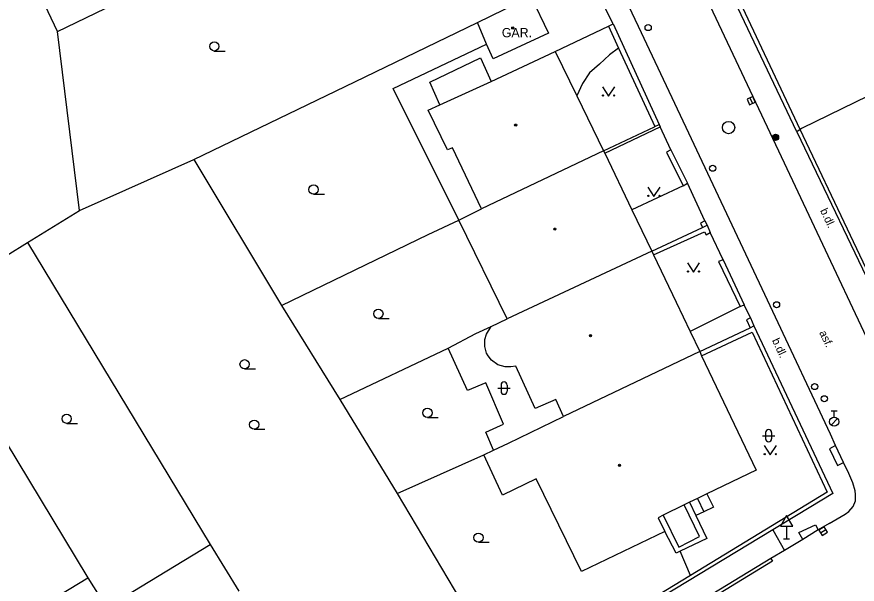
# Model space of a CAD drawing. Extents: x -600391 to -599491, y -1160176 to -1159402.
# Drawn here: x -600105.3 to -600037.1, y -1160099.5 to -1160053.5 of the extents above; entities that cross this region are included whole.
import ezdxf

# ---------------------------------------------------------------- set-up
doc = ezdxf.new("R2010")
doc.units = 0
for name, color, linetype in [('Level 10', 7, 'Continuous'), ('Level 11', 7, 'Continuous'), ('Level 25', 7, 'Continuous'), ('Level 27', 7, 'Continuous'), ('Level 28', 7, 'Continuous'), ('Level 34', 7, 'Continuous'), ('Level 36', 7, 'Continuous'), ('Level 39', 7, 'Continuous'), ('Level 40', 7, 'Continuous'), ('Level 41', 7, 'Continuous'), ('Level 5', 7, 'Continuous'), ('Level 51', 7, 'Continuous'), ('Level 7', 7, 'Continuous'), ('Level 8', 7, 'Continuous')]:
    doc.layers.add(name, color=color, linetype=linetype)

msp = doc.modelspace()

# ---------------------------------------------------------------- linework, layer by layer
at = {"layer": 'Level 10'}
for points in [[(-600033.19, -1160086.1), (-600042.96, -1160065.38), (-600049.67, -1160051.14), (-600054.09, -1160041.8), (-600054.53, -1160040.87)], [(-600038.81, -1160088.3), (-600039.24, -1160087.36), (-600043.9, -1160077.43), (-600044.33, -1160076.51), (-600050.3, -1160063.87), (-600050.73, -1160062.95), (-600054.15, -1160055.73), (-600054.58, -1160054.81), (-600058.59, -1160046.27), (-600059.02, -1160045.36), (-600059.46, -1160044.45), (-600059.92, -1160043.53)], [(-600038.18, -1160089.66), (-600038.81, -1160088.3)], [(-600039.34, -1160094.63), (-600038.05, -1160093.86), (-600037.74, -1160093.66), (-600037.39, -1160093.24), (-600037.19, -1160092.79), (-600037.19, -1160092.28), (-600037.22, -1160091.97), (-600037.41, -1160091.33), (-600037.74, -1160090.57), (-600038.18, -1160089.66)], [(-600039.34, -1160094.63), (-600040.22, -1160095.14)], [(-600040.22, -1160095.14), (-600041.48, -1160095.93)], [(-600041.48, -1160095.93), (-600042.96, -1160096.82)], [(-600042.96, -1160096.82), (-600044.07, -1160097.47)], [(-600044.07, -1160097.47), (-600060.7, -1160107.59), (-600078.93, -1160118.69), (-600104.94, -1160134.34), (-600126.03, -1160147.1), (-600156.25, -1160165.27)]]:
    msp.add_lwpolyline(points, dxfattribs=at)
at = {"layer": 'Level 11'}
for points in [[(-600057.26, -1160054.27), (-600056.87, -1160054.08)], [(-600061.59, -1160056.32), (-600057.26, -1160054.27)], [(-600056.44, -1160056.05), (-600057.18, -1160056.59), (-600057.98, -1160057.33), (-600058.79, -1160058.05), (-600059.36, -1160058.9), (-600059.83, -1160059.92)], [(-600051.18, -1160067.21), (-600055.35, -1160069.16)], [(-600038.81, -1160088.3), (-600039.31, -1160088.55), (-600038.67, -1160089.91), (-600038.18, -1160089.66)], [(-600049.27, -1160092.22), (-600048.74, -1160093.3), (-600049.51, -1160093.67)], [(-600050.67, -1160092.9), (-600050.16, -1160093.98)], [(-600050.02, -1160092.59), (-600049.51, -1160093.67)], [(-600052.82, -1160093.95), (-600051.54, -1160096.53), (-600049.85, -1160095.69), (-600051.12, -1160093.12)], [(-600049.51, -1160093.67), (-600050.16, -1160093.98)], [(-600050.16, -1160093.98), (-600049.28, -1160095.83), (-600051.44, -1160096.88), (-600051.76, -1160097.03), (-600052.67, -1160095.26)], [(-600041.48, -1160095.93), (-600041.79, -1160095.36), (-600040.45, -1160094.73), (-600040.22, -1160095.14)], [(-600043.91, -1160095.14), (-600042.96, -1160096.82)], [(-600044.07, -1160097.47), (-600043.93, -1160097.69), (-600050.62, -1160101.76), (-600060.21, -1160107.58)]]:
    msp.add_lwpolyline(points, dxfattribs=at)
at = {"layer": 'Level 25'}
for radius in [0.25, 0.2, 0.15, 0.1, 0.05]:
    msp.add_circle((-600043.69, -1160063.28), radius, dxfattribs=at)
at = {"layer": 'Level 27'}
for p, q in [((-600045.771, -1160060.081), (-600045.569, -1160060.539)), ((-600040.031, -1160095.385), (-600039.609, -1160095.115))]:
    msp.add_line(p, q, dxfattribs=at)
for points in [[(-600046, -1160060.182), (-600045.798, -1160060.64), (-600045.34, -1160060.438), (-600045.542, -1160059.98)], [(-600039.896, -1160095.595), (-600039.475, -1160095.326), (-600039.744, -1160094.905), (-600040.165, -1160095.174)]]:
    msp.add_lwpolyline(points, close=True, dxfattribs=at)
msp.add_circle((-600047.5, -1160062.49), 0.5, dxfattribs=at)
at = {"layer": 'Level 28'}
for p, q in [((-600039.18, -1160085.485), (-600038.68, -1160085.485)), ((-600038.93, -1160085.985), (-600038.93, -1160085.485)), ((-600039.188, -1160086.632), (-600038.658, -1160086.102))]:
    msp.add_line(p, q, dxfattribs=at)
for centre, radius in [((-600054.03, -1160054.37), 0.25), ((-600048.79, -1160065.79), 0.25), ((-600043.61, -1160076.87), 0.25), ((-600040.52, -1160083.51), 0.25), ((-600039.73, -1160084.5), 0.25), ((-600038.93, -1160086.36), 0.375)]:
    msp.add_circle(centre, radius, dxfattribs=at)
at = {"layer": 'Level 34'}
for p, q in [((-600042.8, -1160094.852), (-600042.8, -1160095.87)), ((-600043.05, -1160095.87), (-600042.55, -1160095.87))]:
    msp.add_line(p, q, dxfattribs=at)
msp.add_lwpolyline([(-600043.3, -1160094.852), (-600042.3, -1160094.852), (-600042.8, -1160093.986)], close=True, dxfattribs=at)
at = {"layer": 'Level 36'}
for p, q in [((-600089.25, -1160056.275), (-600088.375, -1160056.275)), ((-600081.19, -1160067.895), (-600080.315, -1160067.895)), ((-600075.93, -1160077.975), (-600075.055, -1160077.975)), ((-600086.79, -1160082.075), (-600085.915, -1160082.075)), ((-600065.976, -1160083.386), (-600065.976, -1160083.886)), ((-600065.476, -1160083.386), (-600065.476, -1160083.886)), ((-600066.226, -1160083.636), (-600065.226, -1160083.636)), ((-600071.95, -1160086.015), (-600071.075, -1160086.015)), ((-600101.23, -1160086.495), (-600100.355, -1160086.495)), ((-600086.01, -1160086.975), (-600085.135, -1160086.975)), ((-600044.756, -1160087.496), (-600043.756, -1160087.496)), ((-600044.506, -1160087.246), (-600044.506, -1160087.746)), ((-600044.006, -1160087.246), (-600044.006, -1160087.746)), ((-600067.81, -1160096.145), (-600066.935, -1160096.145))]:
    msp.add_line(p, q, dxfattribs=at)
for points in [[(-600057.74, -1160059.19), (-600057.24, -1160059.94), (-600056.74, -1160059.19)], [(-600054.06, -1160067.33), (-600053.56, -1160068.08), (-600053.06, -1160067.33)], [(-600050.85, -1160073.47), (-600050.35, -1160074.22), (-600049.85, -1160073.47)], [(-600044.62, -1160088.3), (-600044.12, -1160089.05), (-600043.62, -1160088.3)]]:
    msp.add_lwpolyline(points, dxfattribs=at)
for centre, radius in [((-600089.25, -1160055.9), 0.375), ((-600057.69, -1160059.89), 0.05), ((-600056.791, -1160059.89), 0.05), ((-600081.19, -1160067.52), 0.375), ((-600054.01, -1160068.03), 0.05), ((-600053.111, -1160068.03), 0.05), ((-600050.8, -1160074.17), 0.05), ((-600049.901, -1160074.17), 0.05), ((-600075.93, -1160077.6), 0.375), ((-600086.79, -1160081.7), 0.375), ((-600071.95, -1160085.64), 0.375), ((-600101.23, -1160086.12), 0.375), ((-600086.01, -1160086.6), 0.375), ((-600044.57, -1160089), 0.05), ((-600043.671, -1160089), 0.05), ((-600067.81, -1160095.77), 0.375)]:
    msp.add_circle(centre, radius, dxfattribs=at)
for centre, start, end in [((-600065.726, -1160083.386), 0, 180), ((-600065.726, -1160083.886), 180, 0), ((-600044.256, -1160087.246), 0, 180), ((-600044.256, -1160087.746), 180, 0)]:
    msp.add_arc(centre, 0.25, start, end, dxfattribs=at)
at = {"layer": 'Level 39'}
for centre, radius in [((-600065.02, -1160054.4), 0.09), ((-600065.02, -1160054.4), 0.0398), ((-600064.78, -1160062.29), 0.09), ((-600064.78, -1160062.29), 0.0398), ((-600061.61, -1160070.73), 0.09), ((-600061.61, -1160070.73), 0.0398), ((-600058.71, -1160079.38), 0.09), ((-600058.71, -1160079.38), 0.0398), ((-600056.36, -1160089.91), 0.09), ((-600056.36, -1160089.91), 0.0398)]:
    msp.add_circle(centre, radius, dxfattribs=at)
at = {"layer": 'Level 5'}
for points in [[(-600067.89, -1160053.97), (-600063.56, -1160051.83)], [(-600063.56, -1160051.83), (-600062.13, -1160054.84)], [(-600067.14, -1160055.71), (-600067.89, -1160053.97)], [(-600062.13, -1160054.84), (-600066.62, -1160056.9)], [(-600066.62, -1160056.9), (-600067.14, -1160055.71)], [(-600066.77, -1160058.74), (-600061.59, -1160056.32)], [(-600061.59, -1160056.32), (-600059.83, -1160059.92), (-600057.65, -1160064.37)], [(-600070.95, -1160060.65), (-600066.77, -1160058.74)], [(-600071.88, -1160061.08), (-600070.95, -1160060.65)], [(-600070.32, -1160064.29), (-600071.88, -1160061.08)], [(-600069.9, -1160064.13), (-600070.32, -1160064.29)], [(-600067.55, -1160069.09), (-600069.9, -1160064.13)], [(-600057.65, -1160064.37), (-600067.55, -1160069.09)], [(-600057.65, -1160064.37), (-600057.55, -1160064.58)], [(-600057.55, -1160064.58), (-600055.35, -1160069.16), (-600053.74, -1160072.53)], [(-600069.41, -1160070.01), (-600067.55, -1160069.09)], [(-600065.47, -1160078.02), (-600069.41, -1160070.01)], [(-600053.74, -1160072.53), (-600065.47, -1160078.02)], [(-600053.74, -1160072.53), (-600053.6, -1160072.83)], [(-600053.6, -1160072.83), (-600051.76, -1160076.66)], [(-600051.76, -1160076.66), (-600050.63, -1160079.03)], [(-600067.15, -1160079.26), (-600066.78, -1160078.63)], [(-600066.78, -1160078.63), (-600065.47, -1160078.02)], [(-600067.29, -1160079.69), (-600067.15, -1160079.26)], [(-600050.63, -1160079.03), (-600049.84, -1160080.67)], [(-600067.3, -1160080.25), (-600067.29, -1160079.69)], [(-600067.14, -1160080.81), (-600067.3, -1160080.25)], [(-600049.84, -1160080.67), (-600060.91, -1160085.95)], [(-600049.84, -1160080.67), (-600049.69, -1160081.01)], [(-600067.03, -1160081.02), (-600067.14, -1160080.81)], [(-600066.76, -1160081.36), (-600067.03, -1160081.02)], [(-600066.22, -1160081.75), (-600066.76, -1160081.36)], [(-600049.69, -1160081.01), (-600045.26, -1160090.3)], [(-600065.65, -1160081.92), (-600066.22, -1160081.75)], [(-600065.18, -1160081.92), (-600065.65, -1160081.92)], [(-600064.78, -1160081.84), (-600065.18, -1160081.92)], [(-600063.21, -1160085.28), (-600064.78, -1160081.84)], [(-600061.53, -1160084.55), (-600063.21, -1160085.28)], [(-600060.91, -1160085.95), (-600061.53, -1160084.55)], [(-600065.37, -1160088.09), (-600060.91, -1160085.95)], [(-600066.58, -1160088.67), (-600065.37, -1160088.09)], [(-600067.38, -1160089.05), (-600066.58, -1160088.67)], [(-600065.86, -1160092.32), (-600067.38, -1160089.05)], [(-600045.26, -1160090.3), (-600049.27, -1160092.22)], [(-600063.13, -1160090.99), (-600065.86, -1160092.32)], [(-600059.45, -1160098.53), (-600063.13, -1160090.99)], [(-600049.27, -1160092.22), (-600050.02, -1160092.59)], [(-600050.67, -1160092.9), (-600051.12, -1160093.12)], [(-600050.02, -1160092.59), (-600050.67, -1160092.9)], [(-600051.12, -1160093.12), (-600052.82, -1160093.95)], [(-600052.82, -1160093.95), (-600053.23, -1160094.15)], [(-600053.23, -1160094.15), (-600052.67, -1160095.26)], [(-600052.67, -1160095.26), (-600059.45, -1160098.53)]]:
    msp.add_lwpolyline(points, dxfattribs=at)
at = {"layer": 'Level 51'}
for points in [[(-600101.98, -1160054.68), (-600106.28, -1160045.59)], [(-600101.98, -1160054.68), (-600084.89, -1160046.42), (-600083.48, -1160045.74)], [(-600077.85, -1160058.77), (-600067.89, -1160053.97)], [(-600100.19, -1160069.23), (-600101.98, -1160054.68)], [(-600074.72, -1160059.33), (-600067.14, -1160055.71)], [(-600071.76, -1160058.81), (-600067.63, -1160056.82)], [(-600067.63, -1160056.82), (-600066.77, -1160058.74)], [(-600090.92, -1160065.08), (-600077.85, -1160058.77)], [(-600070.95, -1160060.65), (-600071.76, -1160058.81)], [(-600069.41, -1160070.01), (-600074.72, -1160059.33)], [(-600100.19, -1160069.23), (-600090.92, -1160065.08)], [(-600090.92, -1160065.08), (-600083.8, -1160076.92)], [(-600104.41, -1160071.82), (-600100.19, -1160069.23)], [(-600071.89, -1160071.18), (-600069.41, -1160070.01)], [(-600083.8, -1160076.92), (-600071.89, -1160071.18)], [(-600107.73, -1160073.86), (-600104.41, -1160071.82)], [(-600104.41, -1160071.82), (-600089.58, -1160096.34)], [(-600112.89, -1160076.92), (-600099.51, -1160099.02)], [(-600083.8, -1160076.92), (-600079.06, -1160084.57)], [(-600046.55, -1160077.02), (-600050.63, -1160079.03)], [(-600068.01, -1160079.21), (-600066.78, -1160078.63)], [(-600070.26, -1160080.38), (-600068.01, -1160079.21)], [(-600079.06, -1160084.57), (-600070.26, -1160080.38)], [(-600068.7, -1160083.83), (-600070.26, -1160080.38)], [(-600067.21, -1160083.2), (-600068.7, -1160083.83)], [(-600065.76, -1160086.56), (-600067.21, -1160083.2)], [(-600079.06, -1160084.57), (-600074.4, -1160092.18)], [(-600067.21, -1160087.22), (-600066.03, -1160086.68)], [(-600066.03, -1160086.68), (-600065.76, -1160086.56)], [(-600066.58, -1160088.67), (-600067.21, -1160087.22)], [(-600074.4, -1160092.18), (-600067.38, -1160089.05)], [(-600098.01, -1160101.44), (-600089.58, -1160096.34)], [(-600089.58, -1160096.34), (-600087.27, -1160100.11)], [(-600050.59, -1160098.83), (-600051.44, -1160096.88)], [(-600109.89, -1160105.3), (-600099.51, -1160099.02)], [(-600099.51, -1160099.02), (-600098.01, -1160101.44)]]:
    msp.add_lwpolyline(points, dxfattribs=at)
at = {"layer": 'Level 7'}
for points in [[(-600041.68, -1160062.64), (-600054.1, -1160036.27), (-600048.77, -1160031.93), (-600048.15, -1160031.43)], [(-600041.96, -1160062.84), (-600054.46, -1160036.54), (-600054.65, -1160036.14), (-600052.36, -1160034.28), (-600051.73, -1160033.77), (-600051.13, -1160033.27), (-600049.14, -1160031.65)], [(-600056.87, -1160054.08), (-600053.15, -1160062.24)], [(-600057.26, -1160054.27), (-600056.44, -1160056.05), (-600053.5, -1160062.41)], [(-600032.98, -1160058.36), (-600041.53, -1160062.53), (-600041.68, -1160062.64)], [(-600053.5, -1160062.41), (-600053.15, -1160062.24)], [(-600053.15, -1160062.24), (-600053.06, -1160062.44)], [(-600057.65, -1160064.37), (-600053.52, -1160062.42), (-600053.5, -1160062.41)], [(-600057.55, -1160064.58), (-600053.06, -1160062.44)], [(-600041.68, -1160062.64), (-600041.96, -1160062.84)], [(-600041.96, -1160062.84), (-600035.07, -1160077.24), (-600029.76, -1160088.61), (-600029.43, -1160089.27), (-600028.95, -1160089.96), (-600028.33, -1160090.62), (-600027.64, -1160091.15)], [(-600029.44, -1160088.45), (-600041.68, -1160062.64)], [(-600052.2, -1160064.3), (-600052.54, -1160064.49), (-600051.18, -1160067.21), (-600050.83, -1160067.01)], [(-600052.2, -1160064.3), (-600050.83, -1160067.01)], [(-600049.42, -1160070.07), (-600049.79, -1160070.25), (-600049.62, -1160070.6)], [(-600049.62, -1160070.6), (-600049.24, -1160070.42)], [(-600049.42, -1160070.07), (-600049.24, -1160070.42)], [(-600049.24, -1160070.42), (-600049, -1160071)], [(-600053.74, -1160072.53), (-600049.62, -1160070.6)], [(-600053.6, -1160072.83), (-600049.46, -1160070.94), (-600049.33, -1160071.19), (-600049, -1160071)], [(-600047.95, -1160073.21), (-600048.31, -1160073.36)], [(-600047.95, -1160073.21), (-600046.24, -1160076.87)], [(-600048.31, -1160073.36), (-600046.55, -1160077.02)], [(-600046.55, -1160077.02), (-600046.24, -1160076.87)], [(-600045.72, -1160077.94), (-600046.05, -1160078.09)], [(-600045.72, -1160077.94), (-600045.44, -1160078.59)], [(-600046.05, -1160078.09), (-600045.75, -1160078.74)], [(-600045.75, -1160078.74), (-600045.44, -1160078.59)], [(-600045.44, -1160078.59), (-600039.03, -1160092.19)], [(-600049.69, -1160081.01), (-600045.6, -1160079.1), (-600039.51, -1160092.08), (-600050.59, -1160098.83), (-600055.99, -1160102.12), (-600055.84, -1160102.36)], [(-600049.84, -1160080.67), (-600045.75, -1160078.74)], [(-600074.4, -1160092.18), (-600065.15, -1160107.78)], [(-600039.03, -1160092.19), (-600043.91, -1160095.14)], [(-600043.91, -1160095.14), (-600055.84, -1160102.36)]]:
    msp.add_lwpolyline(points, dxfattribs=at)
at = {"layer": 'Level 8'}
for points in [[(-600056.87, -1160054.08), (-600058.78, -1160050.22)], [(-600052.2, -1160064.3), (-600053.06, -1160062.44)], [(-600049.42, -1160070.07), (-600050.83, -1160067.01)], [(-600047.95, -1160073.21), (-600049, -1160071)], [(-600045.72, -1160077.94), (-600046.24, -1160076.87)]]:
    msp.add_lwpolyline(points, dxfattribs=at)

# ---------------------------------------------------------------- texts
at = {"layer": 'Level 40'}
for s, rotation, p in [('b.dl. ', 295.2, (-600040.09, -1160069.22)), ('asf.', 295.27, (-600040.16, -1160079.13)), ('b.dl. ', 295.1, (-600044, -1160079.76))]:
    msp.add_text(s, height=0.65, rotation=rotation, dxfattribs=at).set_placement(p)
at = {"layer": 'Level 41'}
msp.add_text('GAR.', height=0.75, dxfattribs=at).set_placement((-600065.91, -1160055.16))

doc.saveas('drawing.dxf')
